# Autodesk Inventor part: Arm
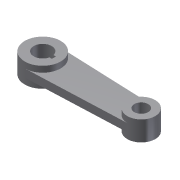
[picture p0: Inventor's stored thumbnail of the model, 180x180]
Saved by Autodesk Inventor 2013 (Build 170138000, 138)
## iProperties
Created: 2009-04
Part Number: Arm
Material: Generic
Document SubType Name: Modeling
Designer: Sham
Density: 1 g/cm^3
Sheet Metal Width: 0.000 mm
Sheet Metal Length: 0.000 mm
Sheet Metal Area: 0.000 mm^2
Author: Sham
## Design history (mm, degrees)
sketch "Sketch1"
  geometry: L1 (27.436, 6.3)-(35.136, 6.3); L2 (35.136, 6.3)-(35.136, -6.3); L3 (35.136, -6.3)-(27.436, -6.3); C1 r 56.25 at (0, 0); C2 r 43.75 at (309, 0); C3 r 21.9 at (309, 0); A1 r 28.15 centre (0, 0) between (27.436, 6.3) and (27.436, -6.3); 1 further point
  constraints: 6 end point, 4 centre point, 3 coincident, 2 point on circle, 1 horizontal, 1 parallel, 1 perpendicular, 1 other
  dimensions: "d0" = 112.5 diameter of C1; "d2" = 87.5 diameter of C2; "d3" = 56.3 diameter of A1; "d4" = 43.8 diameter of C3; "d7" = 12.6 distance of L1.end L2.end; "d8" = 7.7 distance of L1.start L1.end; "d9" = 7.7 distance of L2.end L3.end
extrude "Extrusion1" join sketch "Sketch1" stored distance "d5" = 62.5; taper "d6" = 0 deg
sketch "Sketch2"
  geometry: L1 (2.275, 56.204)-(310.77, 43.714); L2 (2.275, -56.204)-(310.77, -43.714); A1 r 56.25 centre (0, 0) between (2.275, 56.204) and (2.275, -56.204) reference; A2 r 43.75 centre (309, 0) between (310.77, 43.714) and (310.77, -43.714) reference
  constraints: 4 end point, 4 point on circle, 4 tangent
extrude "Extrusion2" join sketch "Sketch2" stored distance "d10" = 25; taper "d11" = 0 deg
body "Solid1"
other parameters: "Thickness" = 0.5, "BendRadius" = 0.5 (= Thickness), "BendReliefWidth" = 0.5 (= Thickness), "BendReliefDepth" = 0.25 (= 0.5 x Thickness), "CornerReliefSize" = 2 (= 4 x Thickness), "SeamGap" = 0.01, "MinimumRemnant" = 1 (= 2 x Thickness), "TransitionRadius" = 0.5 (= BendRadius), "JacobiRadiusSize" = 0.5 (= BendRadius), "GapSize" = 0.5 (= Thickness)
